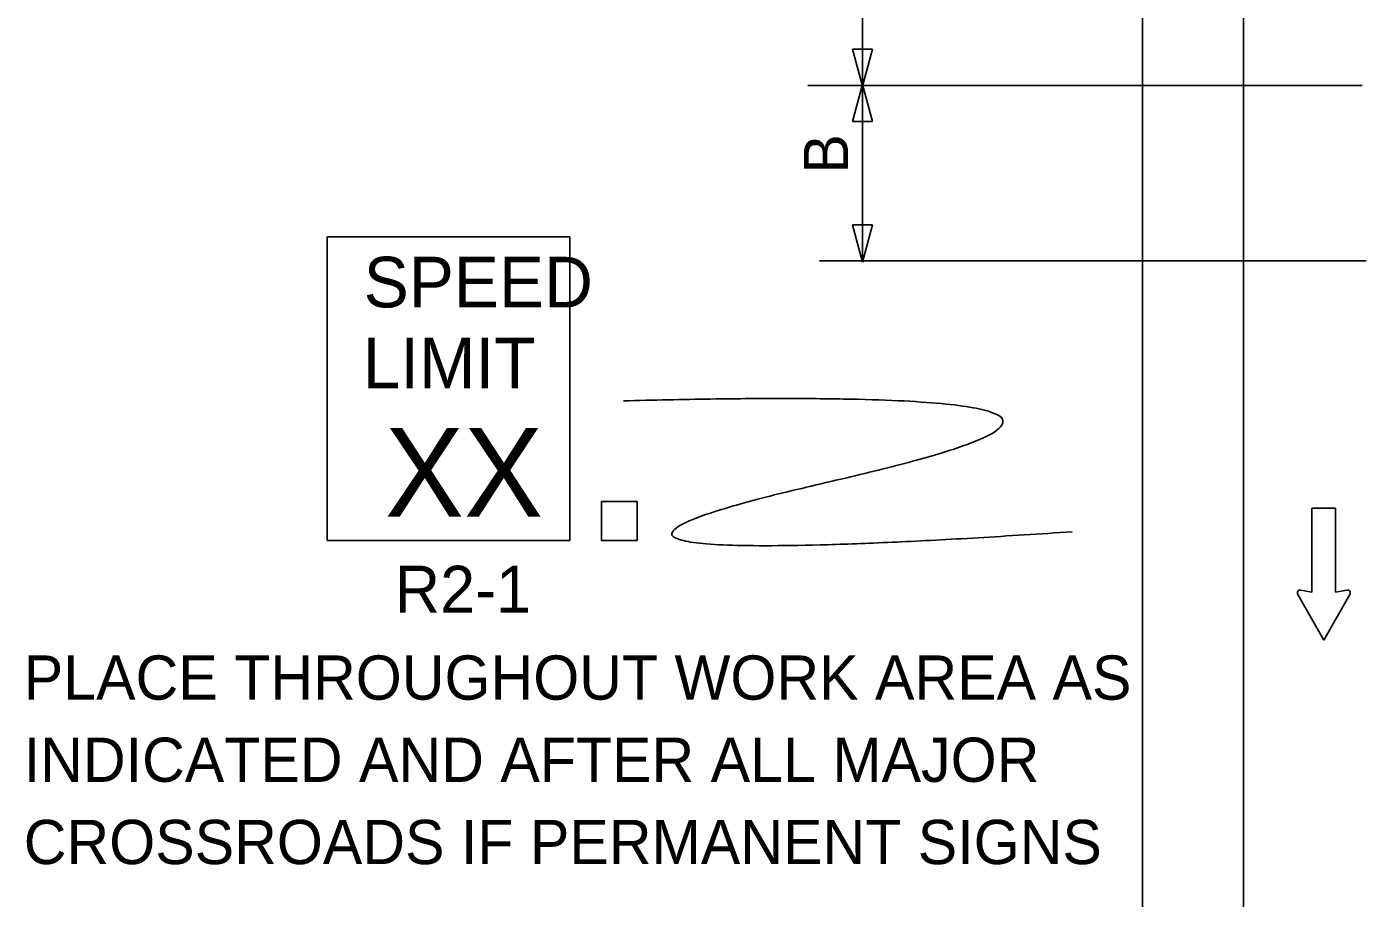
# Model space of a CAD drawing. Extents: x 16646 to 19498, y 2812 to 4437.
# Drawn here: x 16746 to 16958, y 3425.5 to 3563.2 of the extents above; entities that cross this region are included whole.
import ezdxf

# ---------------------------------------------------------------- set-up
doc = ezdxf.new("R2010")
doc.units = 0
for name, color, linetype in [('MT_SCRATCH_LEVEL_E', 7, 'Continuous'), ('PAVT_EDGE_EX', 7, 'Continuous'), ('TRAFFIC_SIGNS_PR', 7, 'Continuous'), ('TYPICAL_EX', 7, 'Continuous'), ('TYPICAL_TEXT_DIMEN_PR', 7, 'Continuous')]:
    doc.layers.add(name, color=color, linetype=linetype)

msp = doc.modelspace()

# ---------------------------------------------------------------- linework, layer by layer
at = {"layer": 'MT_SCRATCH_LEVEL_E'}
for p, q in [((16953.12, 3487.12), (16949.37, 3487.12)), ((16949.37, 3487.12), (16949.37, 3473.86)), ((16953.12, 3487.12), (16949.37, 3487.12)), ((16949.37, 3487.12), (16949.37, 3473.86)), ((16953.12, 3473.86), (16953.12, 3487.12)), ((16953.12, 3473.86), (16953.12, 3487.12)), ((16949.37, 3473.86), (16947.6, 3474.18)), ((16949.37, 3473.86), (16947.6, 3474.18)), ((16954.89, 3474.18), (16953.12, 3473.86)), ((16954.89, 3474.18), (16953.12, 3473.86)), ((16947.12, 3473.49), (16951.26, 3466.25)), ((16947.12, 3473.49), (16951.26, 3466.25)), ((16951.26, 3466.25), (16955.37, 3473.49)), ((16951.26, 3466.25), (16955.37, 3473.49))]:
    msp.add_line(p, q, dxfattribs=at)
for centre, start, end in [((16947.53, 3473.72), 80.0362, 209.7731), ((16947.53, 3473.72), 80.0362, 209.7731), ((16954.97, 3473.72), 330.4248, 99.9638), ((16954.97, 3473.72), 330.4248, 99.9638)]:
    msp.add_arc(centre, 0.463, start, end, dxfattribs=at)
at = {"layer": 'PAVT_EDGE_EX'}
for p, q in [((16938.57, 3998.47), (16938.57, 3231.86)), ((16922.57, 3836.4), (16922.57, 3233.74))]:
    msp.add_line(p, q, dxfattribs=at)
at = {"layer": 'TRAFFIC_SIGNS_PR'}
for p, q in [((16793.57, 3530.02), (16831.97, 3530.02)), ((16793.57, 3482.02), (16793.57, 3530.02)), ((16831.97, 3482.02), (16831.97, 3530.02)), ((16793.57, 3482.02), (16831.97, 3482.02))]:
    msp.add_line(p, q, dxfattribs=at)
msp.add_lwpolyline([(16836.98, 3482.02), (16842.58, 3482.02), (16842.58, 3488.19), (16836.98, 3488.19)], close=True, dxfattribs=at)
msp.add_open_spline([(16840.44, 3504.1), (16940.42, 3506.65), (16807.58, 3476.42), (16911.46, 3483.39)], degree=2, dxfattribs=at)
at = {"layer": 'TYPICAL_EX'}
msp.add_line((16922.57, 3998.47), (16922.57, 3232.23), dxfattribs=at)
at = {"layer": 'TYPICAL_TEXT_DIMEN_PR'}
for p, q in [((16878.26, 3553.86), (16878.26, 3586.14)), ((16878.27, 3553.85), (16876.7, 3559.71)), ((16876.7, 3559.71), (16878.27, 3559.71)), ((16878.27, 3559.71), (16879.84, 3559.71)), ((16879.84, 3559.71), (16878.27, 3553.85)), ((16869.62, 3553.97), (16957.34, 3553.97)), ((16876.7, 3548.26), (16878.27, 3554.12)), ((16878.26, 3526.34), (16878.26, 3553.94)), ((16878.27, 3554.12), (16879.84, 3548.26)), ((16878.27, 3548.26), (16876.7, 3548.26)), ((16879.84, 3548.26), (16878.27, 3548.26)), ((16878.27, 3526.05), (16876.7, 3531.91)), ((16876.7, 3531.91), (16878.27, 3531.91)), ((16878.27, 3531.91), (16879.84, 3531.91)), ((16879.84, 3531.91), (16878.27, 3526.05)), ((16871.47, 3526.25), (16957.97, 3526.25))]:
    msp.add_line(p, q, dxfattribs=at)

# ---------------------------------------------------------------- texts
at = {"layer": 'TRAFFIC_SIGNS_PR'}
for s, height, p in [('SPEED', 8, (16799.33, 3518.88)), ('LIMIT', 8, (16799.17, 3506.08)), ('XX', 14.031, (16802.68, 3485.77)), ('R2-1', 7.44, (16804.24, 3470.58)), ('PLACE THROUGHOUT WORK AREA AS', 7, (16745.54, 3456.84)), ('INDICATED AND AFTER ALL MAJOR', 7, (16745.54, 3443.84)), ('CROSSROADS IF PERMANENT SIGNS', 7, (16745.54, 3430.84))]:
    msp.add_text(s, height=height, dxfattribs=at).set_placement(p)
at = {"layer": 'TYPICAL_TEXT_DIMEN_PR'}
msp.add_text('B', height=7, rotation=90, dxfattribs=at).set_placement((16875.99, 3540.03))

doc.saveas('drawing.dxf')
